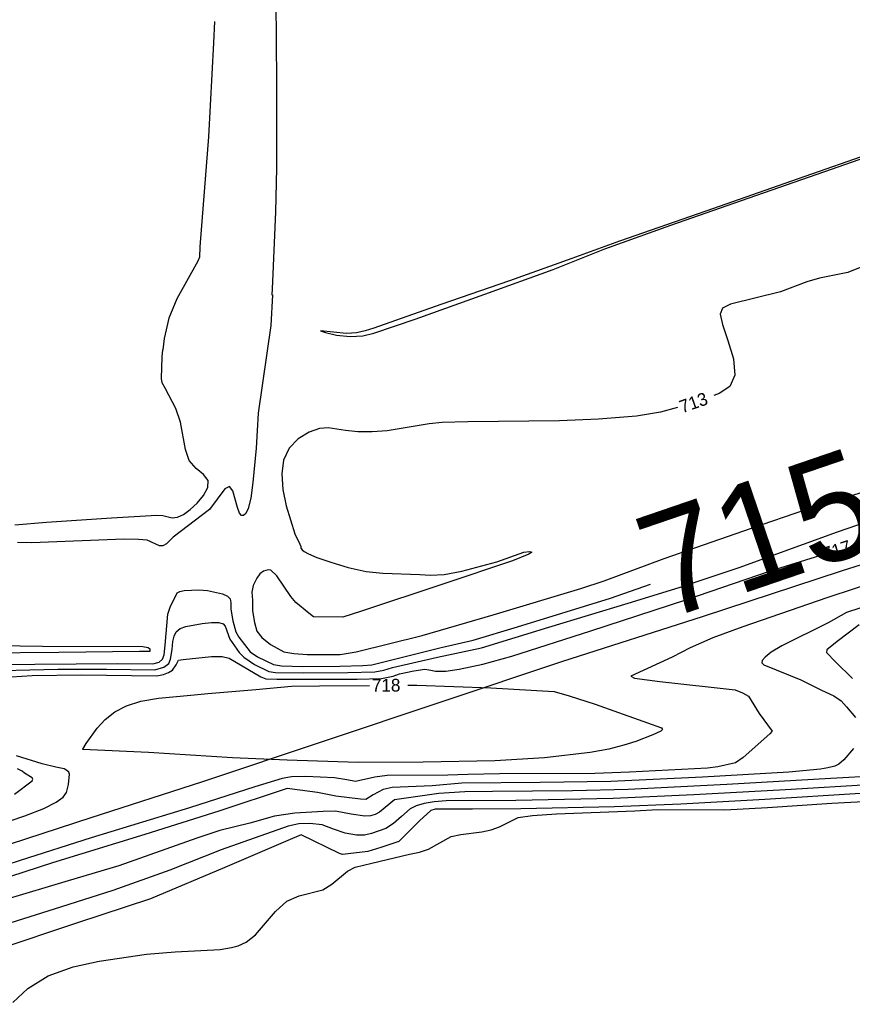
# Model space of a CAD drawing. Extents: x -468548933 to 3387700, y -306089263 to 1207014.
# Drawn here: x 1837809.5 to 1838070.6, y 536156.2 to 536464.3 of the extents above; entities that cross this region are included whole.
import ezdxf

# ---------------------------------------------------------------- set-up
doc = ezdxf.new("R2010")
doc.units = 0
for name, color, linetype in [('DT_X_Contour_Minor', 7, 'Continuous'), ('Level 14', 7, 'Continuous'), ('Level 19', 7, 'Continuous')]:
    doc.layers.add(name, color=color, linetype=linetype)

msp = doc.modelspace()

# ---------------------------------------------------------------- linework, layer by layer
at = {"layer": 'DT_X_Contour_Minor'}
for points in [[(1837888.65, 536377.98), (1837888.9, 536382.21), (1837889.85, 536404.05), (1837890.18, 536417.77), (1837890.08, 536444.87), (1837889.94, 536470.38), (1837890.41, 536500.57), (1837890.79, 536531.65), (1837890.76, 536562.58), (1837890.98, 536577.93), (1837892.31, 536608.92), (1837893.21, 536633.84), (1837893.35, 536663.41), (1837893.77, 536697.64), (1837893.81, 536728.16), (1837893.79, 536738.66)], [(1837870.59, 536463.77), (1837870.28, 536457.07), (1837868.71, 536427.58), (1837866.02, 536393.1), (1837865.84, 536389.83), (1837865.38, 536388.62), (1837858.79, 536376.82), (1837856.29, 536370.71), (1837854.8, 536364.38), (1837854.4, 536360.75)], [(1837992.98, 536392.47), (1838013.73, 536399.83), (1838035.86, 536407.66), (1838064.11, 536417.44), (1838090.12, 536426.57)], [(1838077.52, 536422.75), (1838053.63, 536414.43), (1838024.62, 536404.32), (1837997.59, 536394.83), (1837982.63, 536389.4), (1837963.07, 536382.46), (1837941.6, 536375.02), (1837920.56, 536367.58), (1837917.85, 536366.71), (1837915.15, 536366.12), (1837912.02, 536365.95), (1837903.87, 536366.74), (1837905.36, 536366.2), (1837908.84, 536365.41), (1837913.08, 536364.95), (1837917.06, 536365.21), (1837920.57, 536366.01), (1837933.5, 536370.42), (1837955.32, 536378.27), (1837976.76, 536385.98), (1837992.98, 536392.47)], [(1838073.09, 536386.65), (1838069.19, 536385.03), (1838060.26, 536383.3), (1838056.35, 536382.07), (1838048.04, 536378.96), (1838032.44, 536375.07), (1838029.86, 536373.84), (1838029.12, 536371.95), (1838029.87, 536368.7), (1838031.61, 536363.72), (1838033.29, 536358), (1838033.76, 536352.87), (1838032.15, 536349.33), (1838028.82, 536347.05), (1838027.18, 536346.48)], [(1837888.72, 536378.02), (1837888.25, 536368.39), (1837884.27, 536340.88), (1837883.92, 536335.47), (1837883.67, 536329.93), (1837882.65, 536319.18), (1837881.93, 536314.23), (1837881.15, 536311.06), (1837880.37, 536309.45), (1837879.65, 536308.86), (1837879.01, 536308.87), (1837878.43, 536309.6), (1837877.84, 536311.3), (1837876.35, 536316.6), (1837875.24, 536317.96), (1837873.82, 536317.21), (1837868.99, 536310.68), (1837857.63, 536302.02), (1837855.58, 536299.94), (1837854.41, 536299.28), (1837853.33, 536299.33), (1837849.46, 536301.09), (1837846.75, 536301.36), (1837842.12, 536301.37), (1837813.33, 536300.26), (1837808.78, 536300.36)], [(1837807.97, 536305.94), (1837817.87, 536306.7), (1837838.26, 536308.07), (1837852.49, 536308.95), (1837854.37, 536308.84), (1837857.35, 536308.16), (1837858.96, 536308.29), (1837860.86, 536309.14), (1837862.98, 536310.67), (1837865.15, 536312.72), (1837867.16, 536315.12), (1837868.5, 536317.59), (1837868.59, 536319.83), (1837867.1, 536321.69), (1837864.79, 536323.59), (1837862.67, 536326.08), (1837861.47, 536329.54), (1837859.93, 536338.15), (1837858.42, 536342.42), (1837855.07, 536348.82), (1837854.21, 536350.41), (1837853.92, 536351.82), (1837854.16, 536358.62), (1837854.41, 536360.75)], [(1838015.76, 536342.75), (1838010.43, 536341.26), (1838002.96, 536340), (1837991.03, 536339), (1837978.74, 536338.57), (1837950, 536338.24), (1837942.01, 536338.01), (1837937.9, 536337.58), (1837924.7, 536335.38), (1837920, 536335.07), (1837915.52, 536335.11), (1837911.69, 536335.45), (1837906.24, 536336.34), (1837903.55, 536336.1), (1837900.25, 536334.94), (1837896.83, 536332.85), (1837893.98, 536329.92), (1837892.27, 536326.24), (1837891.66, 536321.9), (1837891.99, 536317.03), (1837893.06, 536311.84), (1837895.82, 536303.13), (1837897.31, 536299.83), (1837897.68, 536299.1), (1837897.63, 536298.6), (1837898.1, 536298.03), (1837898.68, 536297.56), (1837900.01, 536296.83), (1837902.68, 536295.71), (1837907.04, 536294.16), (1837912.47, 536292.55), (1837918.14, 536291.32), (1837923.33, 536290.78), (1837935, 536290.32), (1837938.36, 536290.08), (1837942.6, 536290.34), (1837948.19, 536291.35), (1837959.15, 536294.33), (1837967.61, 536297.34), (1837969.41, 536297.52), (1837970.13, 536297.33), (1837969.2, 536296.71), (1837964.06, 536294.67), (1837942.19, 536287.36), (1837916.7, 536278.79), (1837910.82, 536277.01), (1837901.59, 536277.08), (1837900.12, 536278.23), (1837896.08, 536281.58), (1837894.5, 536283.45), (1837890.1, 536289.96), (1837888.21, 536291.68), (1837887.44, 536291.85), (1837885.98, 536291.38), (1837884.85, 536290.53), (1837883.86, 536289.22), (1837882.68, 536286.94), (1837882.25, 536284.84), (1837882.53, 536282.3), (1837882.51, 536278.96), (1837883.17, 536275.27), (1837883.88, 536272.55), (1837885.44, 536270.54), (1837888.16, 536268.38), (1837892.34, 536266.12), (1837895.48, 536265.59), (1837899.61, 536265.26), (1837910.03, 536265.28), (1837914.97, 536266.06), (1837935.7, 536271.19), (1837957.97, 536277.69), (1837985.5, 536285.99), (1837992.77, 536288.4), (1838011.61, 536295.4), (1838039.02, 536304.89), (1838056, 536310.71), (1838075.15, 536316.53)], [(1837795.13, 536260.01), (1837821.4, 536260.63), (1837836.75, 536260.64), (1837851.9, 536260.46), (1837854.7, 536261.23), (1837856.21, 536262.46), (1837856.78, 536263.84), (1837857.31, 536266.84), (1837857.54, 536269.33), (1837857.89, 536270.97), (1837858.61, 536272.41), (1837859.81, 536273.38), (1837861.56, 536274), (1837866.74, 536274.95), (1837869.63, 536275.3), (1837871.97, 536275.3), (1837873.35, 536274.83), (1837873.97, 536274.1), (1837875.42, 536270.01), (1837878.3, 536265.88), (1837879.73, 536264.39), (1837883.1, 536262.14), (1837887.63, 536259.96), (1837889.71, 536259.62), (1837898.55, 536259.48), (1837912.44, 536259.65), (1837920.87, 536259.84), (1837923.66, 536260.34), (1837926.35, 536261.15), (1837940.52, 536264.41), (1837954.28, 536267.34), (1837975.4, 536273.85), (1838000.32, 536281.35), (1838016.3, 536286.23), (1838035.14, 536292.56), (1838065.96, 536303.68), (1838093.51, 536313.24)], [(1837803.63, 536258.08), (1837813.41, 536258.69), (1837828.76, 536258.9), (1837852.52, 536258.56), (1837854.55, 536258.96), (1837856.19, 536259.57), (1837857.39, 536260.33), (1837858.61, 536261.99), (1837859.3, 536263.43), (1837860.73, 536263.7), (1837869.68, 536264.63), (1837872.96, 536264.61), (1837875.14, 536264.09), (1837885.12, 536258.24), (1837886.7, 536257.65), (1837890.16, 536257.54), (1837915.31, 536257.56), (1837922.96, 536257.76), (1837926.6, 536258.41), (1837928.62, 536259.19), (1837933.04, 536260.17), (1837936.51, 536260.63), (1837938.44, 536260.39), (1837939.86, 536260.07), (1837943.08, 536260.08), (1837947.27, 536260.61), (1837954.71, 536262.19), (1837963.81, 536264.72), (1837988.65, 536272.68), (1838018.39, 536282.35), (1838044.94, 536291.45), (1838060.74, 536296.42)], [(1838080.43, 536288.87), (1838062.62, 536283.07), (1838036.3, 536273.88), (1838026.82, 536270.46), (1838019.78, 536267.35), (1838014.15, 536264.4), (1838001.1, 536258.43), (1838002.33, 536257.85), (1838010.24, 536256.77), (1838033.82, 536254.15), (1838036.19, 536253.24), (1838038.03, 536252.19), (1838041.38, 536246.73), (1838045.43, 536241.17), (1838044.76, 536240.35), (1838036.39, 536232.97), (1838034, 536231.32), (1838028.4, 536230.08), (1838025.23, 536229.65), (1838000.71, 536228.32), (1837989.84, 536227.97), (1837959.94, 536227.85), (1837949.98, 536227.65), (1837943.79, 536227.46), (1837924.73, 536227.28), (1837920.85, 536226.84), (1837914.81, 536225.48), (1837912.09, 536225.93), (1837908.18, 536226.59), (1837899.23, 536226.96), (1837894.68, 536226.91), (1837891.84, 536226.37), (1837883.19, 536223.78), (1837862.79, 536217.16), (1837831.95, 536207.78), (1837809.6, 536200.63), (1837778.12, 536190.46)], [(1837783.76, 536261.81), (1837814.22, 536262.25), (1837840.18, 536262.48), (1837851.29, 536262.36), (1837853.21, 536262.89), (1837854.25, 536263.74), (1837854.76, 536265.14), (1837855.11, 536268.14), (1837855.97, 536277.89), (1837856.69, 536280.07), (1837858.92, 536284.64), (1837859.71, 536285.02), (1837861.08, 536285.33), (1837865.67, 536285.53), (1837868.37, 536285.32), (1837873.14, 536284.23), (1837874.7, 536283.5), (1837875.49, 536282.76), (1837875.67, 536281.44), (1837875.71, 536279.43), (1837876.28, 536275.81), (1837877.31, 536272.31), (1837878.24, 536270.64), (1837881.8, 536266.04), (1837884.09, 536264.52), (1837889.05, 536262.17), (1837891.63, 536261.66), (1837898.31, 536261.47), (1837909.89, 536261.57), (1837917.06, 536261.84), (1837919.92, 536262.06), (1837941.66, 536267.46), (1837951.67, 536269.72), (1837965.58, 536273.89), (1837994.78, 536282.9), (1838007.28, 536287.26)], [(1838097.77, 536287.83), (1838068.73, 536278.43), (1838063.07, 536275.2), (1838048.53, 536268), (1838045.19, 536265.97), (1838043.22, 536264.43), (1838042.31, 536263.33), (1838042.19, 536262.59), (1838042.85, 536262.04), (1838054.44, 536257.28), (1838060.91, 536254.06), (1838064.76, 536252.31), (1838067.15, 536250.7), (1838068.8, 536248.83), (1838071.61, 536245.54)], [(1838072.71, 536274.53), (1838065.86, 536269.36), (1838062.61, 536266.68), (1838062.53, 536265.9), (1838065.35, 536262.99), (1838070.62, 536257.68)], [(1837708.18, 536269.22), (1837723.42, 536269.07), (1837723.65, 536269.2), (1837724.55, 536269.35), (1837730.64, 536269.44), (1837756.7, 536268.86), (1837788.4, 536268.26), (1837816.67, 536267.89), (1837848.14, 536267.79), (1837849.77, 536267.47), (1837850.35, 536267.08), (1837850.3, 536266.24), (1837849.81, 536266.15), (1837847.04, 536266.15), (1837821.72, 536265.84), (1837797.53, 536265.66), (1837765.37, 536265.85), (1837748.69, 536265.97), (1837725.26, 536266.18), (1837725.17, 536266.05), (1837723.64, 536265.84), (1837717.13, 536265.67), (1837709.15, 536266.45)], [(1837931.2, 536255.64), (1837933.99, 536255.64), (1837957.27, 536254.78), (1837977.06, 536253.69), (1837981.85, 536252.27), (1837990, 536249.69), (1838010.78, 536242.29), (1838011.12, 536241.75), (1838010.57, 536241.26), (1838008.03, 536240.05), (1838002.73, 536237.99), (1837998.98, 536236.79), (1837994.29, 536235.6), (1837988.41, 536234.51), (1837974.05, 536232.9), (1837958.49, 536231.94), (1837935.97, 536231.47), (1837915.65, 536231.35), (1837893.36, 536232.11), (1837876.25, 536232.82), (1837849.93, 536234.54), (1837829.33, 536235.43), (1837829.32, 536235.59), (1837830.35, 536237.36), (1837833.8, 536242.16), (1837836.32, 536244.89), (1837839.31, 536247.27), (1837842.95, 536249.19), (1837847.52, 536250.63), (1837853.04, 536251.58), (1837863.19, 536252.46), (1837868.5, 536253.03)], [(1837868.5, 536253.03), (1837883.56, 536254.31), (1837894.78, 536255.28), (1837903.51, 536255.47), (1837919.2, 536255.58)], [(1838070.98, 536235.76), (1838067.98, 536232.22), (1838066.42, 536230.86), (1838065.15, 536230.29), (1838062.91, 536229.67), (1838060.57, 536229.25), (1838050.69, 536228.32), (1838023.64, 536226.77), (1837994.89, 536225.4), (1837972.67, 536225.11), (1837948.19, 536224.89), (1837938.81, 536224.09), (1837926.26, 536223.53), (1837923.45, 536222.88), (1837920.39, 536221.28), (1837918.08, 536219.75), (1837916.41, 536219.88), (1837908.61, 536220.8), (1837902.89, 536222.01), (1837897.36, 536222.76), (1837893.32, 536223.24), (1837871.92, 536216.17), (1837848.71, 536208.78), (1837819.78, 536199.9), (1837792.98, 536191.22)], [(1837797.47, 536210.04), (1837811.13, 536214.69), (1837817.08, 536217.01), (1837820.97, 536218.94), (1837823.1, 536220.53), (1837824.13, 536221.93), (1837824.83, 536224.46), (1837825.15, 536227.73), (1837824.86, 536228.34), (1837824.3, 536228.9), (1837823.43, 536229.36), (1837820.87, 536229.97), (1837816.5, 536230.93), (1837808.45, 536233.5)], [(1838093.75, 536228.07), (1838063.81, 536226.34), (1838031.21, 536224.49), (1838000.29, 536222.89), (1837982.88, 536222.51), (1837957.81, 536222.29), (1837949.09, 536222.23), (1837940.97, 536221.62), (1837927.03, 536219.69), (1837922.33, 536215.85), (1837920.95, 536215.09), (1837919.47, 536214.65), (1837917.72, 536214.57), (1837913.45, 536215.21), (1837908.5, 536216.13), (1837904.66, 536216.04), (1837895.78, 536215.53), (1837889.42, 536214.54), (1837881.68, 536212.41), (1837872.28, 536210.03), (1837865.07, 536207.62), (1837840.6, 536199), (1837824.65, 536194.27), (1837805.15, 536188.46)], [(1837807.85, 536221.49), (1837813.38, 536225.64), (1837813.65, 536226.16), (1837813.45, 536226.54), (1837811.05, 536228.08), (1837810.31, 536228.7), (1837808.81, 536229.43)], [(1838073.13, 536221.64), (1838043.13, 536219.79), (1838016.84, 536218.35), (1837995.98, 536217.47), (1837966.65, 536216.84), (1837951.45, 536216.76), (1837939.8, 536216.77), (1837938.38, 536216.33), (1837934.92, 536213.05), (1837928.35, 536206.62), (1837922.75, 536204.71), (1837918.71, 536203.47), (1837910.71, 536202.58), (1837909.74, 536202.83), (1837897.8, 536208.74), (1837893.63, 536206.95), (1837873.87, 536198.43), (1837850.53, 536188.63), (1837827.33, 536180.96), (1837802.25, 536172.69)], [(1838077.38, 536224.49), (1838049.64, 536222.84), (1838020.89, 536221.25), (1837995.61, 536220.11), (1837965.07, 536219.52), (1837943.24, 536219.36), (1837939.43, 536219.05), (1837936.3, 536218.54), (1837933.82, 536217.8), (1837931.95, 536216.82), (1837929.23, 536214.48), (1837926.75, 536212.23), (1837924.3, 536210.68), (1837919.79, 536209.08), (1837917.65, 536208.6), (1837915.07, 536208.57), (1837911.61, 536209.22), (1837907.95, 536210.52), (1837904.34, 536211.84), (1837900.51, 536212.29), (1837896.99, 536212.13), (1837893.72, 536211.46), (1837872.7, 536204.04), (1837856.59, 536197.63), (1837838.67, 536191.25), (1837820.29, 536185.44), (1837806.69, 536181.06)], [(1837947.83, 536208.84), (1837954.4, 536209.61), (1837957.39, 536210.32), (1837959.94, 536211.26), (1837965.76, 536214.12), (1837970.28, 536214.8), (1837977.81, 536215.26), (1838002.37, 536216.22), (1838009.58, 536216.6), (1838030.63, 536216.53), (1838044.02, 536217.27), (1838064.16, 536218.62), (1838092.03, 536220.15)], [(1837807.31, 536156.18), (1837812.02, 536160.51), (1837818.38, 536164.47), (1837826.28, 536167.27), (1837834.46, 536169.04), (1837849.28, 536171.33), (1837858.28, 536171.98), (1837872.4, 536172.74), (1837875.95, 536173.35), (1837878.01, 536173.91), (1837880.55, 536175.07), (1837883.41, 536177.3), (1837889.74, 536184.71), (1837893.31, 536187.91), (1837897.16, 536189.63), (1837904.51, 536191.43), (1837907.42, 536193.19), (1837912.25, 536197.31), (1837914.69, 536198.56), (1837919.92, 536199.87), (1837931.78, 536202.67), (1837934.87, 536203.31), (1837937.67, 536204.23), (1837944.83, 536208.18), (1837947.83, 536208.84)]]:
    msp.add_lwpolyline(points, dxfattribs=at)
at = {"layer": 'Level 14'}
msp.add_lwpolyline([(1837751.38, 536188.04), (1837791.13, 536200.82), (1837831.94, 536214.15), (1837866.96, 536225.47), (1837979.86, 536263.14), (1838023.59, 536277.14), (1838067.23, 536291.44), (1838108.15, 536304.5)], dxfattribs=at)

# ---------------------------------------------------------------- texts
at = {"layer": 'Level 19'}
for s, height, rotation, p in [('713', 4, 19.3488, (1838017.24, 536340.87)), ('715', 33, 18.8847, (1838011.27, 536275.76)), ('717', 4, 17.4638, (1838062.04, 536294.73)), ('718', 4, 0.3896, (1837919.97, 536253.58))]:
    msp.add_text(s, height=height, rotation=rotation, dxfattribs=at).set_placement(p)

doc.saveas('drawing.dxf')
